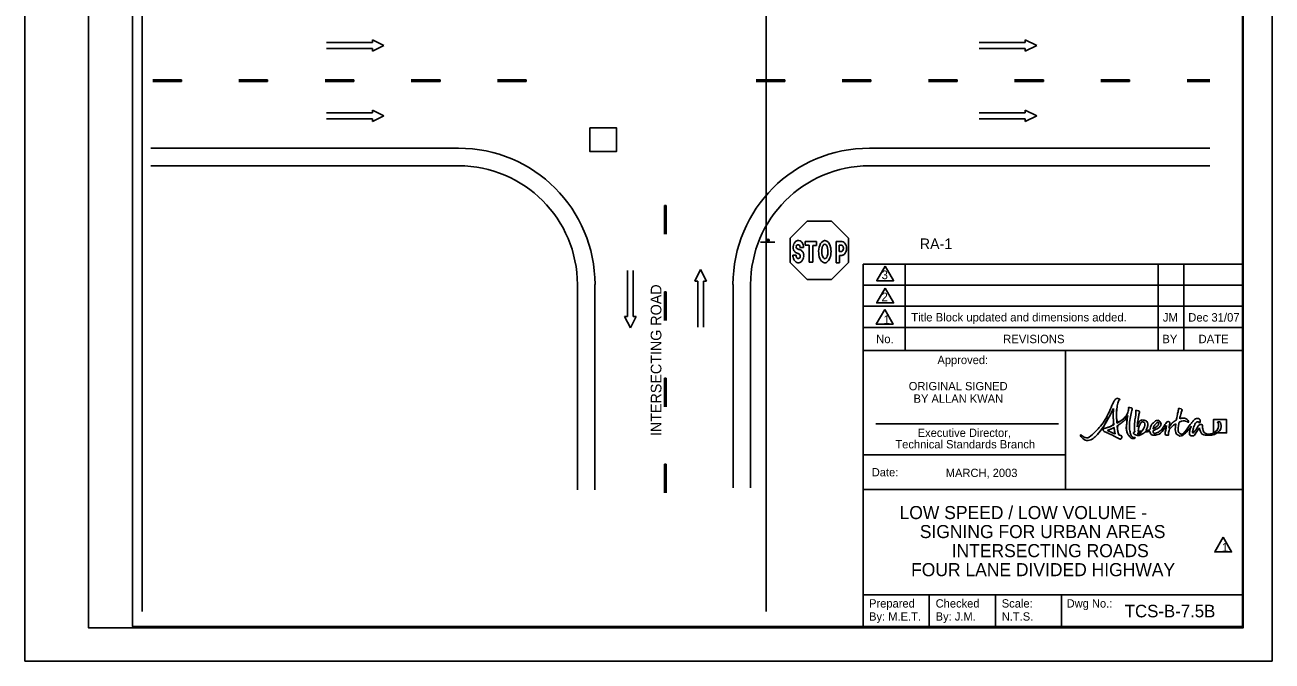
# Model space of a CAD drawing. Extents: x 1373 to 1583, y 130 to 399.
# Drawn here: x 1373.1 to 1583.1, y 130 to 237.1 of the extents above; entities that cross this region are included whole.
import ezdxf

# ---------------------------------------------------------------- set-up
doc = ezdxf.new("R2010")
doc.units = 0
for name, color, linetype in [('Level 10', 7, 'Continuous'), ('Level 17', 7, 'Continuous'), ('Level 2', 7, 'Continuous'), ('Level 53', 7, 'Continuous'), ('Level 60', 7, 'Continuous')]:
    doc.layers.add(name, color=color, linetype=linetype)

msp = doc.modelspace()

# ---------------------------------------------------------------- linework, layer by layer
at = {"layer": 'Level 10'}
for p, q in [((1392.81, 390.25), (1392.81, 138.3)), ((1497.88, 390.01), (1497.88, 138.3)), ((1423.84, 234.09), (1431.58, 234.09)), ((1431.58, 233.12), (1423.84, 233.12)), ((1431.58, 234.57), (1433.51, 233.6)), ((1431.58, 234.09), (1431.58, 234.57)), ((1433.51, 233.6), (1431.58, 232.63)), ((1431.58, 232.63), (1431.58, 233.12)), ((1533.75, 234.09), (1541.49, 234.09)), ((1541.49, 233.12), (1533.75, 233.12)), ((1541.49, 234.57), (1543.42, 233.6)), ((1541.49, 234.09), (1541.49, 234.57)), ((1543.42, 233.6), (1541.49, 232.63)), ((1541.49, 232.63), (1541.49, 233.12)), ((1431.58, 222.73), (1433.51, 221.76)), ((1431.58, 222.25), (1431.58, 222.73)), ((1541.49, 222.73), (1543.42, 221.76)), ((1541.49, 222.25), (1541.49, 222.73)), ((1423.84, 222.25), (1431.58, 222.25)), ((1431.58, 221.28), (1423.84, 221.28)), ((1433.51, 221.76), (1431.58, 220.8)), ((1431.58, 220.8), (1431.58, 221.28)), ((1533.75, 222.25), (1541.49, 222.25)), ((1541.49, 221.28), (1533.75, 221.28)), ((1543.42, 221.76), (1541.49, 220.8)), ((1541.49, 220.8), (1541.49, 221.28)), ((1446.08, 216.31), (1394.25, 216.31)), ((1572.59, 216.31), (1515.25, 216.31)), ((1446.08, 213.35), (1394.25, 213.35)), ((1572.59, 213.35), (1515.25, 213.35)), ((1504.17, 199.59), (1503.56, 199.59)), ((1504.46, 199.97), (1504.46, 200.6)), ((1504.46, 200.6), (1506.37, 200.6)), ((1505.12, 199.97), (1504.46, 199.97)), ((1505.12, 197.15), (1505.12, 199.97)), ((1506.37, 199.96), (1505.74, 199.96)), ((1505.74, 199.96), (1505.74, 197.15)), ((1506.37, 200.6), (1506.37, 199.96)), ((1507.7, 200.15), (1507.72, 200.15)), ((1507.72, 200.76), (1507.74, 200.76)), ((1509.63, 197.04), (1509.63, 200.63)), ((1509.63, 200.63), (1510.64, 200.63)), ((1510.15, 199.99), (1510.15, 198.94)), ((1510.54, 199.99), (1510.15, 199.99)), ((1510.54, 199.99), (1510.15, 199.99)), ((1510.15, 199.99), (1510.15, 198.94)), ((1502.35, 198.31), (1502.91, 198.31)), ((1502.53, 197.59), (1502.52, 197.6)), ((1510.15, 198.94), (1510.54, 198.94)), ((1510.15, 198.94), (1510.54, 198.94)), ((1510.23, 198.27), (1510.6, 198.27)), ((1510.23, 198.27), (1510.23, 197.04)), ((1510.58, 198.27), (1510.23, 198.27)), ((1474.51, 195.72), (1474.51, 187.98)), ((1475.48, 187.98), (1475.48, 195.72)), ((1485.87, 193.94), (1486.84, 195.87)), ((1486.84, 195.87), (1487.8, 193.94)), ((1505.74, 197.15), (1505.12, 197.15)), ((1510.23, 197.04), (1509.63, 197.04)), ((1466.08, 158.79), (1466.08, 193.35)), ((1469.04, 158.79), (1469.04, 193.35)), ((1486.35, 193.94), (1485.87, 193.94)), ((1486.35, 186.19), (1486.35, 193.94)), ((1487.8, 193.94), (1487.32, 193.94)), ((1487.32, 193.94), (1487.32, 186.19)), ((1492.29, 193.35), (1492.29, 159.15)), ((1495.25, 193.35), (1495.25, 159.15)), ((1474.03, 187.98), (1475, 186.05)), ((1474.51, 187.98), (1474.03, 187.98)), ((1475, 186.05), (1475.96, 187.98)), ((1475.96, 187.98), (1475.48, 187.98))]:
    msp.add_line(p, q, dxfattribs=at)
msp.add_lwpolyline([(1511.74, 197.06), (1508.87, 194.2), (1504.79, 194.2), (1501.92, 197.06), (1501.92, 201.15), (1504.79, 204.02), (1508.87, 204.02), (1511.74, 201.15)], close=True, dxfattribs=at)
for centre, radius, start, end in [((1446.08, 193.35), 22.97, 0, 90), ((1515.25, 193.35), 22.97, 90, 180), ((1446.08, 193.35), 20, 0, 90), ((1515.25, 193.35), 20, 90, 180), ((1503.95, 199.64), 1.52, 157.7332, 177.1392), ((1503.77, 199.59), 1.34, 174.8171, 195.9183), ((1503.54, 199.77), 1.09, 123.3662, 155.6734), ((1503.22, 199.71), 0.302, 164.131, 238.1476), ((1503.26, 199.76), 0.331, 113.8064, 172.2407), ((1503.29, 200.11), 0.665, 46.1369, 121.3987), ((1503.23, 199.73), 0.346, 47.3017, 109.0119), ((1503.07, 199.67), 0.506, 350.4412, 39.3244), ((1503.01, 199.75), 1.12, 14.564, 49.0063), ((1502.61, 199.57), 1.55, 0.6952, 17.1452), ((1510.48, 199.65), 0.354, 35.1198, 79.3117), ((1510.48, 199.65), 0.354, 35.1198, 79.3117), ((1510.58, 200.04), 0.596, 44.8528, 85.0441), ((1510.32, 199.54), 0.55, 8.6031, 34.217), ((1510.32, 199.54), 0.55, 8.6031, 34.217), ((1510.3, 199.47), 0.585, 350.3417, 15.2342), ((1510.3, 199.47), 0.585, 350.3417, 15.2342), ((1510.4, 199.78), 0.915, 29.2241, 48.5308), ((1510.4, 199.78), 0.915, 29.2241, 48.5308), ((1510.38, 199.69), 0.972, 13.0674, 33.762), ((1509.51, 199.4), 1.89, 3.3903, 15.6597), ((1509.88, 199.44), 1.52, 349.7521, 2.7916), ((1509.88, 199.44), 1.52, 349.7521, 2.7916), ((1504.23, 198.39), 1.88, 182.3841, 204.9519), ((1503.37, 199.55), 0.952, 200.4481, 235.1107), ((1503.7, 198.23), 1.34, 208.4154, 233.6553), ((1505.81, 205), 6.9, 244.4624, 248.8312), ((1503.76, 198.3), 0.856, 179.0172, 193.5172), ((1503.36, 198.13), 0.43, 186.8728, 222.7449), ((1503.3, 198.17), 0.419, 230.6966, 271.4573), ((1504.17, 201.23), 2.1, 237.9816, 250.979), ((1503.27, 198.14), 0.388, 275.4374, 314.0625), ((1503.21, 198.14), 0.435, 34.2083, 74.1552), ((1502.94, 197.89), 1.47, 46.2465, 67.9263), ((1503.1, 198.14), 0.516, 326.253, 358.7323), ((1503.14, 197.97), 0.977, 293.1413, 324.9906), ((1503.22, 198.18), 0.399, 352.5761, 30.4776), ((1502.54, 198.37), 1.7, 325.5092, 343.2894), ((1505.94, 200.57), 2.57, 219.479, 223.4261), ((1502.67, 198.22), 1.53, 5.9097, 21.9865), ((1502.03, 198.22), 2.16, 351.247, 3.9864), ((1510.45, 199.34), 0.406, 281.9191, 325.7868), ((1510.45, 199.34), 0.406, 281.9191, 325.7868), ((1510.62, 198.48), 0.207, 259.7909, 293.5419), ((1510.44, 199.13), 0.882, 286.602, 299.8091), ((1510.35, 199.4), 0.522, 326.5086, 357.0313), ((1510.35, 199.4), 0.522, 326.5086, 357.0313), ((1510.62, 198.9), 0.597, 295.3838, 322.6188), ((1510.37, 199.18), 0.968, 318.2922, 338.6031), ((1510.37, 199.18), 0.968, 318.2922, 338.6031), ((1509.43, 199.56), 1.98, 338.3153, 348.6699), ((1503.29, 197.64), 0.612, 232.0536, 292.7397)]:
    msp.add_arc(centre, radius, start, end, dxfattribs=at)
for centre, major_axis, ratio, start_param, end_param in [((1507.75, 198.89), (-0.01, -1.87), 0.558644, 4.129576, 6.939747), ((1507.75, 198.89), (-0.01, -1.87), 0.558644, 3.185857, 4.129398), ((1507.75, 198.93), (0.01, -1.22), 0.432619, 3.890436, 7.165085), ((1507.75, 198.93), (0.01, -1.22), 0.432619, 3.239639, 3.888884), ((1507.75, 198.93), (0.01, -1.22), 0.432619, 0.881967, 3.190734), ((1507.75, 198.89), (-0.01, -1.87), 0.558644, 0.656861, 3.168126)]:
    msp.add_ellipse(centre, major_axis=major_axis, ratio=ratio, start_param=start_param, end_param=end_param, dxfattribs=at)
at = {"layer": 'Level 17'}
for p, q in [((1496.93, 200.47), (1499.35, 200.47)), ((1578.17, 135.56), (1578.17, 135.56))]:
    msp.add_line(p, q, dxfattribs=at)
msp.add_lwpolyline([(1468.17, 219.72), (1472.69, 219.72), (1472.69, 215.78), (1468.17, 215.78)], close=True, dxfattribs=at)
for radius in [0.242, 0.121]:
    msp.add_circle((1498.15, 200.75), radius, dxfattribs=at)
at = {"layer": 'Level 2'}
for p, q in [((1399.41, 227.85), (1394.57, 227.85)), ((1394.57, 227.56), (1399.41, 227.56)), ((1399.41, 227.56), (1399.41, 227.85)), ((1413.92, 227.85), (1409.09, 227.85)), ((1409.09, 227.56), (1413.92, 227.56)), ((1413.92, 227.56), (1413.92, 227.85)), ((1428.44, 227.85), (1423.6, 227.85)), ((1423.6, 227.56), (1428.44, 227.56)), ((1428.44, 227.56), (1428.44, 227.85)), ((1442.95, 227.85), (1438.12, 227.85)), ((1438.12, 227.56), (1442.95, 227.56)), ((1442.95, 227.56), (1442.95, 227.85)), ((1457.47, 227.85), (1452.63, 227.85)), ((1452.63, 227.56), (1457.47, 227.56)), ((1457.47, 227.56), (1457.47, 227.85)), ((1501.01, 227.85), (1496.17, 227.85)), ((1496.17, 227.56), (1501.01, 227.56)), ((1501.01, 227.56), (1501.01, 227.85)), ((1515.52, 227.85), (1510.68, 227.85)), ((1510.68, 227.56), (1515.52, 227.56)), ((1515.52, 227.56), (1515.52, 227.85)), ((1530.04, 227.85), (1525.2, 227.85)), ((1525.2, 227.56), (1530.04, 227.56)), ((1530.04, 227.56), (1530.04, 227.85)), ((1544.55, 227.85), (1539.71, 227.85)), ((1539.71, 227.56), (1544.55, 227.56)), ((1544.55, 227.56), (1544.55, 227.85)), ((1559.07, 227.85), (1554.23, 227.85)), ((1554.23, 227.56), (1559.07, 227.56)), ((1559.07, 227.56), (1559.07, 227.85)), ((1572.59, 227.85), (1568.74, 227.85)), ((1568.74, 227.56), (1572.59, 227.56)), ((1480.75, 206.66), (1480.75, 201.82)), ((1481.04, 206.66), (1480.75, 206.66)), ((1481.04, 201.82), (1481.04, 206.66)), ((1480.75, 192.14), (1480.75, 187.31)), ((1481.04, 192.14), (1480.75, 192.14)), ((1481.04, 187.31), (1481.04, 192.14)), ((1480.75, 177.63), (1480.75, 172.79)), ((1481.04, 177.63), (1480.75, 177.63)), ((1481.04, 172.79), (1481.04, 177.63)), ((1480.75, 163.12), (1480.75, 158.28)), ((1481.04, 163.12), (1480.75, 163.12)), ((1481.04, 158.28), (1481.04, 163.12))]:
    msp.add_line(p, q, dxfattribs=at)
at = {"layer": 'Level 53'}
msp.add_line((1573.8, 168.4), (1573.25, 168.4), dxfattribs=at)
msp.add_lwpolyline([(1573.8, 168.4), (1575.41, 168.4), (1575.41, 170.63), (1573.18, 170.63), (1573.18, 168.4), (1573.25, 168.4)], dxfattribs=at)
for points, degree in [([(1559.81, 167.59), (1559.57, 167.63), (1559.26, 167.95), (1559.16, 168.49), (1558.99, 169.46), (1559.09, 170.41), (1559.38, 171.83), (1559.43, 172.1), (1559.62, 172.57), (1559.03, 172.66), (1558.85, 172.69), (1558.94, 172.59), (1558.89, 172.35), (1558.67, 171.29), (1557.8, 170.53), (1556.93, 170.02), (1556.84, 171.23), (1556.88, 172.57), (1557.11, 173.4), (1557.3, 174.09), (1557.53, 173.97), (1557.24, 174.11), (1556.94, 174.27), (1556.62, 174.06), (1556.36, 173.54), (1556.1, 173.03), (1554.91, 170.21), (1553, 168.31), (1552.02, 167.34), (1551.13, 167.84), (1550.96, 167.99), (1550.81, 168.11), (1550.76, 167.92), (1550.94, 167.73), (1551.73, 166.88), (1552.88, 167.36), (1553.3, 167.79), (1554.47, 168.95), (1555.82, 171.45), (1556.37, 172.51), (1556.32, 171.91), (1556.3, 170.91), (1556.41, 169.74), (1555.82, 169.45), (1555.29, 169.28), (1555.04, 169.21), (1554.77, 169.14), (1554.6, 169.03), (1554.59, 168.91), (1554.59, 168.77), (1554.77, 168.65), (1555.03, 168.53), (1555.5, 168.31), (1556.87, 167.66), (1557.21, 167.46), (1557.5, 167.29), (1557.64, 167.42), (1557.73, 167.6), (1557.84, 167.84), (1557.53, 167.98), (1557.24, 168.07), (1557.12, 168.46), (1557.03, 169), (1556.97, 169.59), (1557.67, 170.02), (1558.35, 170.59), (1558.75, 171.3), (1558.65, 170.71), (1558.39, 168.68), (1559.03, 167.82), (1559.18, 167.63), (1559.49, 167.42), (1559.79, 167.45), (1559.94, 167.47), (1560.01, 167.56), (1559.99, 167.59), (1559.98, 167.62), (1559.9, 167.58), (1559.81, 167.59)], 3), ([(1556.93, 170.02), (1556.84, 171.23), (1556.88, 172.57), (1557.11, 173.4), (1557.3, 174.09), (1557.53, 173.97), (1557.24, 174.11), (1556.94, 174.27), (1556.62, 174.06), (1556.36, 173.54), (1556.1, 173.03), (1554.91, 170.21), (1553, 168.31), (1552.02, 167.34), (1551.13, 167.84), (1550.96, 167.99), (1550.81, 168.11), (1550.76, 167.92), (1550.94, 167.73), (1551.73, 166.88), (1552.88, 167.36), (1553.3, 167.79), (1554.47, 168.95), (1555.82, 171.45), (1556.37, 172.51)], 3), ([(1556.37, 172.51), (1556.32, 171.91), (1556.3, 170.91), (1556.41, 169.74)], 2), ([(1559.81, 167.59), (1559.57, 167.63), (1559.26, 167.95), (1559.16, 168.49), (1558.99, 169.46), (1559.09, 170.41), (1559.38, 171.83), (1559.43, 172.1), (1559.62, 172.57), (1559.03, 172.66), (1558.85, 172.69), (1558.94, 172.59), (1558.89, 172.35), (1558.67, 171.29), (1557.8, 170.53), (1556.93, 170.02)], 3), ([(1567.5, 170.77), (1567.57, 171.07), (1567.64, 171.37), (1567.73, 171.67), (1567.8, 171.94), (1568.02, 172.4), (1567.45, 172.49), (1567.26, 172.52), (1567.34, 172.43), (1567.28, 172.18), (1567.17, 171.73), (1567.03, 171.13), (1566.93, 170.54)], 3), ([(1556.97, 169.59), (1557.67, 170.02), (1558.35, 170.59), (1558.75, 171.3)], 2), ([(1558.75, 171.3), (1558.65, 170.71), (1558.39, 168.68), (1559.03, 167.82), (1559.18, 167.63), (1559.49, 167.42), (1559.79, 167.45), (1559.94, 167.47), (1560.01, 167.56), (1559.99, 167.59), (1559.98, 167.62), (1559.9, 167.58), (1559.81, 167.59)], 3), ([(1560.35, 169.43), (1560.4, 170), (1560.49, 170.7), (1560.62, 171.34), (1560.67, 171.61), (1560.85, 172.07), (1560.27, 172.16), (1560.08, 172.19), (1560.11, 172.1), (1560.13, 171.85), (1560.15, 171.52), (1559.78, 169.48), (1559.97, 168.58)], 3), ([(1561.79, 168.77), (1562.2, 169.45), (1562.17, 170.35), (1561.56, 170.51), (1560.86, 170.69), (1560.5, 170), (1560.35, 169.43)], 3), ([(1560.5, 168.64), (1560.59, 169.36), (1560.97, 170.35), (1561.43, 170.19), (1561.7, 170.1), (1561.56, 169.26), (1561.21, 168.71)], 3), ([(1563.01, 168.8), (1563.11, 168.82), (1563.2, 168.85), (1563.27, 168.89), (1564.15, 169.28), (1564.45, 169.87), (1564.23, 170.23), (1564.02, 170.57), (1563.41, 170.47), (1562.93, 169.96), (1562.69, 169.71), (1562.51, 169.28), (1562.49, 168.89)], 3), ([(1565.69, 169.21), (1565.74, 169.49), (1565.83, 169.79), (1565.84, 170), (1565.84, 170.22), (1565.69, 170.26), (1565.64, 170.28), (1565.51, 170.32), (1565.36, 170.25), (1565.21, 170.04), (1564.85, 169.54), (1564.41, 168.76), (1563.73, 168.43), (1563.24, 168.19), (1563.03, 168.43), (1563.01, 168.8)], 3), ([(1563.49, 169.91), (1563.78, 170.19), (1563.93, 170.17), (1563.97, 170.1), (1564.05, 169.94), (1563.7, 169.37), (1563.04, 169.07)], 3), ([(1566.93, 170.54), (1566.45, 170.27), (1566.01, 169.81), (1565.69, 169.21)], 2), ([(1572.56, 168.2), (1571.64, 168.2), (1571.41, 168.91), (1571.36, 169.27), (1571.33, 169.5), (1571.38, 169.84), (1570.98, 169.79), (1570.7, 169.76), (1570.44, 169.21), (1570.08, 168.75), (1569.77, 168.35), (1569.64, 168.39), (1569.71, 168.73), (1569.8, 169.16), (1570.15, 170.16), (1570.56, 170.24), (1570.75, 170.27), (1570.82, 169.94), (1570.91, 170.15), (1570.99, 170.35), (1570.91, 170.8), (1570.49, 170.8), (1570.19, 170.8), (1569.84, 170.49), (1569.55, 170.13), (1569.29, 169.82), (1568.01, 167.93), (1567.47, 168.34), (1567.22, 168.53), (1567.24, 169.3), (1567.4, 170.22)], 3), ([(1567.4, 170.22), (1568.04, 170.47), (1568.57, 170.39), (1568.87, 170.24), (1569.02, 170.17), (1569.04, 170.18), (1568.97, 170.35), (1568.88, 170.59), (1568.37, 170.96), (1567.56, 170.79), (1567.54, 170.78), (1567.52, 170.78), (1567.5, 170.77)], 3), ([(1573.18, 170.63), (1573.18, 170.63), (1573.18, 168.4), (1573.18, 168.4), (1573.18, 168.4), (1573.25, 168.4), (1573.25, 168.4), (1573.73, 168.69), (1574.06, 169.25), (1574.06, 169.7), (1574.06, 170.09), (1573.85, 170.08), (1573.87, 170.13), (1573.94, 170.29), (1574.43, 170.2), (1574.46, 169.64), (1574.49, 169.17), (1574.24, 168.71), (1573.8, 168.4), (1573.8, 168.4), (1575.41, 168.4), (1575.41, 168.4), (1575.41, 168.4), (1575.41, 170.63), (1575.41, 170.63), (1575.41, 170.63), (1573.18, 170.63), (1573.18, 170.63)], 3), ([(1573.25, 168.4), (1573.73, 168.69), (1574.06, 169.25), (1574.06, 169.7), (1574.06, 170.09), (1573.85, 170.08), (1573.87, 170.13), (1573.94, 170.29), (1574.43, 170.2), (1574.46, 169.64), (1574.49, 169.17), (1574.24, 168.71), (1573.8, 168.4)], 3), ([(1556.41, 169.74), (1555.82, 169.45), (1555.29, 169.28), (1555.04, 169.21), (1554.77, 169.14), (1554.6, 169.03), (1554.59, 168.91), (1554.59, 168.77), (1554.77, 168.65), (1555.03, 168.53), (1555.5, 168.31), (1556.87, 167.66), (1557.21, 167.46), (1557.5, 167.29), (1557.64, 167.42), (1557.73, 167.6), (1557.84, 167.84), (1557.53, 167.98), (1557.24, 168.07)], 3), ([(1555.34, 168.8), (1555.65, 168.92), (1556.04, 169.08), (1556.46, 169.3)], 2), ([(1555.34, 168.8), (1555.65, 168.92), (1556.04, 169.08), (1556.46, 169.3), (1556.51, 168.83), (1556.57, 168.48), (1556.64, 168.23), (1556.34, 168.34), (1555.91, 168.52), (1555.34, 168.8)], 3), ([(1556.64, 168.23), (1556.34, 168.34), (1555.91, 168.52), (1555.34, 168.8)], 2), ([(1556.46, 169.3), (1556.51, 168.83), (1556.57, 168.48), (1556.64, 168.23)], 2), ([(1557.24, 168.07), (1557.12, 168.46), (1557.03, 169), (1556.97, 169.59)], 2), ([(1559.97, 168.58), (1559.72, 168.5), (1559.62, 168.31), (1559.94, 168.11), (1560.16, 167.97), (1560.65, 167.93), (1561.15, 168.17), (1561.33, 168.26), (1561.48, 168.38), (1561.61, 168.53)], 3), ([(1560.43, 168.21), (1560.46, 168.24), (1560.48, 168.28), (1560.48, 168.33), (1560.48, 168.36), (1560.48, 168.39), (1560.48, 168.42)], 3), ([(1560.63, 168.21), (1560.55, 168.2), (1560.48, 168.2), (1560.43, 168.21)], 2), ([(1560.48, 168.42), (1560.61, 168.43), (1560.8, 168.44), (1561.04, 168.46)], 2), ([(1561.21, 168.71), (1560.99, 168.68), (1560.75, 168.66), (1560.5, 168.64)], 2), ([(1561.04, 168.46), (1560.91, 168.33), (1560.77, 168.24), (1560.63, 168.21)], 2), ([(1561.61, 168.53), (1561.9, 168.57), (1562.21, 168.61), (1562.49, 168.67)], 2), ([(1562.49, 168.89), (1562.28, 168.85), (1562.05, 168.81), (1561.79, 168.77)], 2), ([(1562.49, 168.67), (1562.54, 168.28), (1562.8, 167.98), (1563.39, 168.03), (1564.24, 168.11), (1564.99, 169.15), (1565.28, 169.65)], 3), ([(1563.04, 169.07), (1563.09, 169.37), (1563.25, 169.7), (1563.49, 169.91)], 2), ([(1565.28, 169.65), (1565.22, 169.11), (1564.88, 167.94), (1565.47, 168), (1565.7, 168.02), (1565.6, 168.06), (1565.62, 168.26), (1565.67, 168.97), (1566.26, 169.57), (1566.84, 169.94)], 3), ([(1566.84, 169.94), (1566.74, 169.07), (1566.77, 168.3), (1567.17, 168.05), (1567.89, 167.6), (1568.91, 168.79), (1569.47, 169.52)], 3), ([(1569.47, 169.52), (1569.19, 168.87), (1569.02, 168.04), (1569.45, 167.92), (1569.96, 167.77), (1570.36, 168.61), (1570.82, 169.25)], 3), ([(1570.82, 169.25), (1570.88, 168.79), (1571.18, 168), (1572.42, 168), (1572.98, 168), (1573.45, 168.15), (1573.8, 168.4)], 3), ([(1573.25, 168.4), (1573.04, 168.28), (1572.81, 168.2), (1572.56, 168.2)], 2)]:
    msp.add_open_spline(points, degree=degree, dxfattribs=at)
at = {"layer": 'Level 60'}
for p, q in [((1373.06, 398.98), (1373.06, 129.98)), ((1583.06, 129.98), (1583.06, 398.98)), ((1514.21, 190.33), (1514.21, 196.8)), ((1578.06, 196.8), (1514.21, 196.8)), ((1521.3, 190.33), (1521.3, 196.8)), ((1563.89, 196.8), (1563.89, 182.25)), ((1568.2, 196.8), (1568.2, 182.25)), ((1578.06, 193.25), (1514.21, 193.25)), ((1514.21, 182.25), (1514.21, 190.33)), ((1578.06, 189.7), (1514.21, 189.7)), ((1521.3, 182.25), (1521.3, 190.33)), ((1578.06, 186.16), (1514.21, 186.16)), ((1514.21, 135.79), (1514.21, 182.25)), ((1514.21, 182.25), (1578.06, 182.25)), ((1514.21, 182.25), (1578.06, 182.25)), ((1514.21, 182.25), (1578.06, 182.25)), ((1548.26, 182.25), (1548.26, 158.84)), ((1548.28, 182.25), (1548.28, 182.25)), ((1516.32, 169.94), (1547.12, 169.94)), ((1514.21, 164.7), (1548.26, 164.7)), ((1514.21, 158.84), (1578.06, 158.84)), ((1514.21, 141.11), (1578.06, 141.11)), ((1525.34, 135.79), (1525.34, 141.11)), ((1536.47, 135.79), (1536.47, 141.11)), ((1547.6, 141.11), (1547.6, 135.79)), ((1529.68, 135.79), (1529.68, 135.79)), ((1578.06, 135.79), (1578.06, 135.79)), ((1373.06, 129.98), (1583.06, 129.98))]:
    msp.add_line(p, q, dxfattribs=at)
for points in [[(1383.77, 393.31), (1578.17, 393.31), (1578.17, 135.56), (1383.77, 135.56)], [(1391.18, 393.17), (1578.06, 393.17), (1578.06, 135.79), (1391.18, 135.79)], [(1517.83, 189.14), (1516.41, 186.67), (1519.25, 186.67)], [(1574.83, 150.83), (1573.41, 148.36), (1576.25, 148.36)]]:
    msp.add_lwpolyline(points, close=True, dxfattribs=at)
for points in [[(1517.91, 196.47), (1516.52, 194.05)], [(1519.31, 194.05), (1517.91, 196.47)], [(1516.52, 194.05), (1516.49, 194), (1519.33, 194), (1519.31, 194.05)], [(1517.91, 192.75), (1516.52, 190.33)], [(1519.31, 190.33), (1517.91, 192.75)], [(1516.52, 190.33), (1516.49, 190.28), (1519.33, 190.28), (1519.31, 190.33)]]:
    msp.add_lwpolyline(points, dxfattribs=at)

# ---------------------------------------------------------------- texts
at = {"layer": 'Level 10'}
msp.add_text('INTERSECTING ROAD', height=1.8, rotation=90, dxfattribs=at).set_placement((1480.23, 167.85))
at = {"layer": 'Level 17'}
for s, height, p in [('RA-1', 1.8, (1523.73, 199.32)), ('ORIGINAL SIGNED', 1.4, (1521.88, 175.56)), ('BY ALLAN KWAN', 1.4, (1522.69, 173.46))]:
    msp.add_text(s, height=height, dxfattribs=at).set_placement(p)
at = {"layer": 'Level 60'}
for s, height, p in [('3', 1.45, (1517.3, 194.27)), ('2', 1.45, (1517.29, 190.55)), ('1', 1.45, (1517.61, 186.72)), ('Title Block updated and dimensions added.', 1.419, (1522.3, 187.15)), ('JM', 1.419, (1564.66, 187.13)), ('Dec 31/07', 1.419, (1568.94, 187.13)), ('No.', 1.419, (1516.39, 183.49)), ('REVISIONS', 1.419, (1537.77, 183.49)), ('BY', 1.419, (1564.58, 183.49)), ('DATE', 1.419, (1570.68, 183.49)), ('Date:', 1.4, (1515.65, 161.07)), ('LOW SPEED / LOW VOLUME -', 2.2, (1520.33, 153.88)), ('SIGNING FOR URBAN AREAS', 2.2, (1523.74, 150.68)), ('INTERSECTING ROADS', 2.2, (1529.11, 147.47)), ('1', 1.45, (1574.61, 148.42)), ('FOUR LANE DIVIDED HIGHWAY', 2.2, (1522.27, 144.27)), ('Prepared', 1.4, (1515.2, 138.99)), ('Checked', 1.4, (1526.41, 138.99)), ('Scale:', 1.4, (1537.54, 138.99)), ('Dwg No.:', 1.4, (1548.46, 138.99)), ('By: M.E.T.', 1.4, (1515.2, 136.79)), ('By: J.M.', 1.4, (1526.41, 136.79)), ('N.T.S.', 1.4, (1537.54, 136.79))]:
    msp.add_text(s, height=height, rotation=360, dxfattribs=at).set_placement(p)
for s, height, p in [('Approved:', 1.4, (1526.71, 179.97)), ('Executive Director,', 1.4, (1523.38, 167.71)), ('Technical Standards Branch', 1.4, (1519.63, 165.78)), ('MARCH, 2003', 1.4, (1528.11, 160.96)), ('TCS-B-7.5B', 2.116, (1558.25, 137.34))]:
    msp.add_text(s, height=height, dxfattribs=at).set_placement(p)

doc.saveas('drawing.dxf')
